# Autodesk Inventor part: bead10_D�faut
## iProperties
Created: 2011-01
Part Number: bead10_D�faut
Document SubType Name: Modeling
Designer: eric
Density: 1 g/cm^3
Mass: 0.0717017 g
Surface Area: 2.42642 cm^2
Volume: 0.0717017 cm^3
Author: eric
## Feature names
1. Base1
